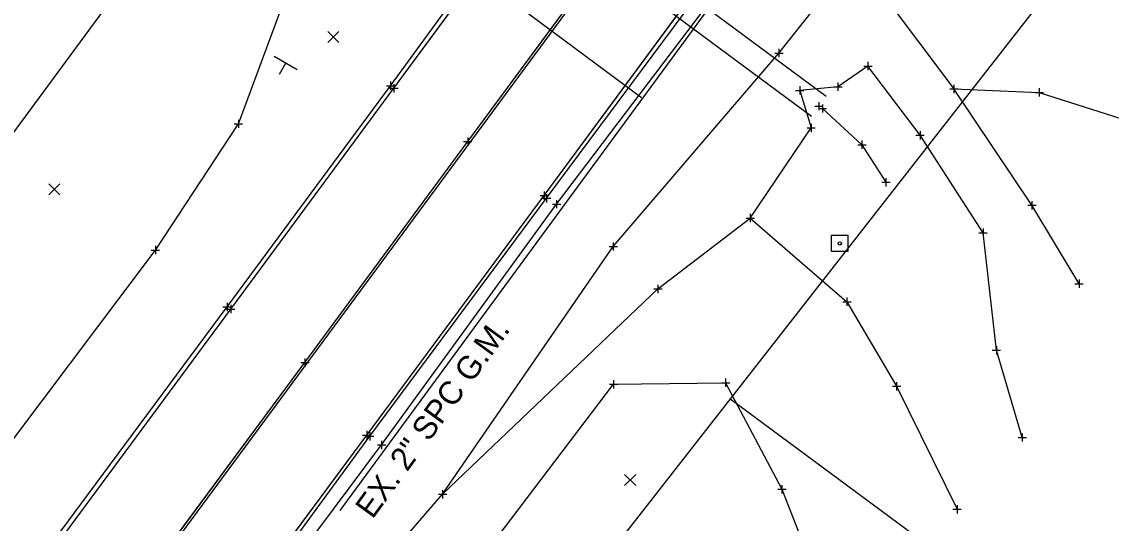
# Model space of a CAD drawing. Extents: x 1324089 to 1329959, y 459099 to 462017.
# Drawn here: x 1325717.7 to 1325849.1, y 460869.9 to 460930.3 of the extents above; entities that cross this region are included whole.
import ezdxf

# ---------------------------------------------------------------- set-up
doc = ezdxf.new("R2010")
doc.units = 0
for name, color, linetype in [('DR_X_Ditch', 7, 'Continuous'), ('DR_X_Storm_Sewer', 7, 'Continuous'), ('DV_X_Property_Line', 7, 'Continuous'), ('PM_X_CL_Double_Solid', 7, 'Continuous'), ('PM_X_Edge_Line', 7, 'Continuous'), ('PM_X_Surveyed_Line', 7, 'Continuous'), ('PV_X_EOP', 7, 'Continuous'), ('RW_X_CL', 7, 'Continuous'), ('RW_X_Fee_RW', 7, 'Continuous'), ('SN_X_Public', 7, 'Continuous'), ('SV_P_Control_Cells_Set', 7, 'Continuous'), ('SV_X_Break_Lines', 7, 'Continuous'), ('SV_X_Random_Point', 7, 'Continuous'), ('SV_X_Shot_Marker', 7, 'Continuous'), ('UT_X_Gas', 7, 'Continuous'), ('UT_X_Gas_Text', 7, 'Continuous'), ('VG_X_Tree_Line_Lt', 7, 'Continuous')]:
    doc.layers.add(name, color=color, linetype=linetype)

msp = doc.modelspace()

# ---------------------------------------------------------------- linework, layer by layer
at = {"layer": 'DR_X_Ditch'}
for points in [[(1325814.27, 460919.9), (1325819.02, 460915.54), (1325821.92, 460911.01)], [(1325618.01, 460663.53), (1325627.67, 460681.57), (1325647.09, 460709.52), (1325667.43, 460737.33), (1325687.6, 460764.77), (1325707.75, 460792.17), (1325728.3, 460821.9), (1325747.65, 460849.3), (1325768.45, 460873.4), (1325794.43, 460898.16), (1325805.56, 460906.69), (1325812.9, 460917.55)]]:
    msp.add_lwpolyline(points, dxfattribs=at)
at = {"layer": 'DR_X_Storm_Sewer'}
for p, q in [((1325764.82, 460958.35), (1325814.73, 460921.37)), ((1325763.03, 460955.94), (1325812.94, 460918.96))]:
    msp.add_line(p, q, dxfattribs=at)
at = {"layer": 'DV_X_Property_Line'}
msp.add_line((1326000.99, 460738.77), (1325803.1, 460884.89), dxfattribs=at)
at = {"layer": 'PM_X_CL_Double_Solid'}
for p, q in [((1325771.48, 460915.92), (1325790.62, 460941.82)), ((1325751.85, 460889.28), (1325771.48, 460915.92)), ((1325731.56, 460861.89), (1325751.85, 460889.28))]:
    msp.add_line(p, q, dxfattribs=at)
at = {"layer": 'PM_X_Edge_Line'}
for p, q in [((1325762.59, 460922.34), (1325781.84, 460948.46)), ((1325780.72, 460909.4), (1325799.76, 460935.26)), ((1325742.91, 460895.72), (1325762.59, 460922.34)), ((1325759.31, 460880.54), (1325780.72, 460909.4)), ((1325722.79, 460868.47), (1325742.91, 460895.72)), ((1325740.27, 460854.83), (1325759.31, 460880.54))]:
    msp.add_line(p, q, dxfattribs=at)
at = {"layer": 'PM_X_Surveyed_Line'}
for points in [[(1325476.47, 460534.64), (1325497.31, 460562.92), (1325518.31, 460591.4), (1325539.27, 460619.83), (1325559.79, 460647.38), (1325579.72, 460674.06), (1325600.34, 460701.82), (1325621.69, 460730.61), (1325640.88, 460756.72), (1325660.89, 460784.38), (1325681.35, 460812.31), (1325701.97, 460840.18), (1325722.79, 460868.47), (1325742.91, 460895.72), (1325762.59, 460922.34), (1325781.84, 460948.46), (1325803.18, 460977.15), (1325823.47, 461004.35), (1325843.8, 461031.8), (1325864.41, 461059.13), (1325882.73, 461083.84)], [(1325487.31, 460531.49), (1325505.56, 460556.21), (1325527.38, 460585.35), (1325547.88, 460612.77), (1325568.5, 460640.75), (1325588.53, 460667.69), (1325609.18, 460695.62), (1325629.78, 460723.42), (1325649.85, 460750.69), (1325670.06, 460778.36), (1325689.99, 460805.97), (1325710.73, 460833.83), (1325731.56, 460861.89), (1325751.85, 460889.28), (1325771.48, 460915.92), (1325790.62, 460941.82), (1325811.71, 460970.27), (1325832.15, 460997.96), (1325852.52, 461025.38), (1325872.84, 461052.92), (1325891.56, 461078.18)], [(1325496.02, 460524.26), (1325516.97, 460552.29), (1325536.74, 460578.69), (1325557.07, 460606.11), (1325577.39, 460633.55), (1325597.52, 460661.26), (1325617.8, 460689.11), (1325638.48, 460716.73), (1325658.71, 460744.05), (1325678.83, 460771.46), (1325699, 460798.96), (1325719.69, 460827.08), (1325740.27, 460854.83), (1325759.31, 460880.54), (1325780.72, 460909.4), (1325799.76, 460935.26), (1325820.52, 460963.73), (1325840.72, 460991.07), (1325861.64, 461019.05), (1325881.76, 461046.3), (1325900.52, 461071.57)]]:
    msp.add_lwpolyline(points, dxfattribs=at)
at = {"layer": 'PV_X_EOP'}
for points in [[(1325599.85, 460702.28), (1325620.93, 460731.2), (1325640.13, 460757.25), (1325660.19, 460784.82), (1325680.81, 460812.72), (1325701.43, 460840.57), (1325722.31, 460868.78), (1325742.47, 460895.99), (1325762.18, 460922.64), (1325781.4, 460948.97), (1325780.32, 460951.92), (1325801.56, 460978.26), (1325816.22, 460999.3), (1325818.01, 460999.23), (1325822.67, 461005.05), (1325842.97, 461032.46), (1325863.41, 461059.87), (1325881.77, 461084.58), (1325817.82, 460998.91)], [(1325599.89, 460659.68), (1325606.14, 460668.13), (1325605.32, 460670.67), (1325618.61, 460688.48), (1325639.21, 460716.24), (1325659.3, 460743.54), (1325679.42, 460770.95), (1325699.67, 460798.43), (1325720.28, 460826.77), (1325740.7, 460854.48), (1325759.66, 460880.4), (1325781, 460909.09), (1325800.15, 460934.9), (1325820.98, 460963.36), (1325841.65, 460990.38), (1325860.1, 461014.66), (1325864.14, 461018.09), (1325883.16, 461043.3), (1325885.35, 461048.43), (1325901.49, 461070.93), (1325836.64, 460984.43)]]:
    msp.add_lwpolyline(points, dxfattribs=at)
at = {"layer": 'RW_X_CL'}
msp.add_line((1325484.96, 460527.54), (1326057.93, 461303.2), dxfattribs=at)
at = {"layer": 'RW_X_Fee_RW'}
for p, q in [((1325448.76, 460554.27), (1326011.05, 461315.47)), ((1325947.56, 461069.64), (1325722.65, 460781.99))]:
    msp.add_line(p, q, dxfattribs=at)
at = {"layer": 'SN_X_Public'}
for p, q in [((1325748.14, 460926.2), (1325750.92, 460924.6)), ((1325749.53, 460925.4), (1325748.73, 460924.01)), ((1325749.53, 460925.4), (1325749.53, 460925.4))]:
    msp.add_line(p, q, dxfattribs=at)
at = {"layer": 'SV_P_Control_Cells_Set'}
msp.add_lwpolyline([(1325815.35, 460904.64), (1325817.33, 460904.64), (1325817.33, 460902.65), (1325815.35, 460902.65), (1325815.35, 460904.64)], dxfattribs=at)
msp.add_circle((1325816.34, 460903.64), 0.2, dxfattribs=at)
at = {"layer": 'SV_X_Break_Lines'}
for points in [[(1325602.57, 460725.5), (1325611.53, 460737.32), (1325631.62, 460762.97), (1325651.12, 460791.06), (1325670.21, 460817.47), (1325692.28, 460846.55), (1325713.18, 460875.42), (1325733.82, 460902.84), (1325743.83, 460918.05), (1325750.81, 460936.82), (1325754.6, 460945.57), (1325761.22, 460957.49), (1325755.79, 460950.52)], [(1325640.49, 460715.25), (1325660.58, 460742.6), (1325680.68, 460770), (1325700.88, 460797.61), (1325721.48, 460825.86), (1325741.85, 460853.59), (1325761.1, 460879.35), (1325782.21, 460908.37), (1325801.61, 460934.01)], [(1325838.36, 460880.25), (1325835.24, 460890.77), (1325833.64, 460904.93), (1325826.04, 460916.67), (1325819.75, 460925.01), (1325816.13, 460922.53), (1325811.52, 460922.08), (1325812.9, 460917.55)], [(1325845.21, 460898.78), (1325839.53, 460908.24), (1325830.12, 460922.26)], [(1325805.56, 460906.69), (1325817.21, 460896.61), (1325823.21, 460886.42), (1325830.5, 460871.6)], [(1325674.96, 460732.24), (1325693.51, 460759.08), (1325711.73, 460788.03), (1325735.94, 460817.21), (1325756.26, 460844.61), (1325775.03, 460868.18), (1325789.08, 460886.67), (1325802.59, 460886.85), (1325809.37, 460874.01), (1325815.93, 460857.25)]]:
    msp.add_lwpolyline(points, dxfattribs=at)
at = {"layer": 'SV_X_Random_Point'}
for p, q in [((1325754.6, 460927.85), (1325755.93, 460929.19)), ((1325754.6, 460929.19), (1325755.93, 460927.85)), ((1325720.96, 460909.49), (1325722.29, 460910.83)), ((1325720.96, 460910.83), (1325722.29, 460909.49)), ((1325790.41, 460874.45), (1325791.74, 460875.78)), ((1325790.41, 460875.78), (1325791.74, 460874.45))]:
    msp.add_line(p, q, dxfattribs=at)
at = {"layer": 'SV_X_Shot_Marker'}
for p, q in [((1325808.51, 460926.58), (1325809.51, 460926.58)), ((1325809.01, 460927.08), (1325809.01, 460926.08)), ((1325809.01, 460926.58), (1325809.01, 460926.58)), ((1325819.25, 460925.01), (1325820.25, 460925.01)), ((1325819.75, 460925.51), (1325819.75, 460924.51)), ((1325819.75, 460925.01), (1325819.75, 460925.01)), ((1325761.68, 460922.64), (1325762.68, 460922.64)), ((1325762.09, 460922.34), (1325763.09, 460922.34)), ((1325762.18, 460923.14), (1325762.18, 460922.14)), ((1325762.18, 460922.64), (1325762.18, 460922.64)), ((1325762.59, 460922.84), (1325762.59, 460921.84)), ((1325762.59, 460922.34), (1325762.59, 460922.34)), ((1325811.02, 460922.08), (1325812.02, 460922.08)), ((1325811.52, 460922.58), (1325811.52, 460921.58)), ((1325811.52, 460922.08), (1325811.52, 460922.08)), ((1325815.63, 460922.53), (1325816.63, 460922.53)), ((1325816.13, 460923.03), (1325816.13, 460922.03)), ((1325816.13, 460922.53), (1325816.13, 460922.53)), ((1325829.62, 460922.26), (1325830.62, 460922.26)), ((1325829.62, 460922.26), (1325830.62, 460922.26)), ((1325830.12, 460922.76), (1325830.12, 460921.76)), ((1325830.12, 460922.76), (1325830.12, 460921.76)), ((1325830.12, 460922.26), (1325830.12, 460922.26)), ((1325830.12, 460922.26), (1325830.12, 460922.26)), ((1325840.4, 460922.34), (1325840.4, 460921.34)), ((1325813.83, 460920.68), (1325813.83, 460919.68)), ((1325839.9, 460921.84), (1325840.9, 460921.84)), ((1325840.4, 460921.84), (1325840.4, 460921.84)), ((1325813.33, 460920.18), (1325814.33, 460920.18)), ((1325813.77, 460919.9), (1325814.77, 460919.9)), ((1325813.83, 460920.18), (1325813.83, 460920.18)), ((1325814.27, 460920.4), (1325814.27, 460919.4)), ((1325814.27, 460919.9), (1325814.27, 460919.9)), ((1325743.33, 460918.05), (1325744.33, 460918.05)), ((1325743.83, 460918.55), (1325743.83, 460917.55)), ((1325743.83, 460918.05), (1325743.83, 460918.05)), ((1325812.9, 460918.05), (1325812.9, 460917.05)), ((1325812.9, 460918.05), (1325812.9, 460917.05)), ((1325812.4, 460917.55), (1325813.4, 460917.55)), ((1325812.4, 460917.55), (1325813.4, 460917.55)), ((1325812.9, 460917.55), (1325812.9, 460917.55)), ((1325812.9, 460917.55), (1325812.9, 460917.55)), ((1325825.54, 460916.67), (1325826.54, 460916.67)), ((1325826.04, 460917.17), (1325826.04, 460916.17)), ((1325826.04, 460916.67), (1325826.04, 460916.67)), ((1325770.98, 460915.92), (1325771.98, 460915.92)), ((1325771.48, 460916.42), (1325771.48, 460915.42)), ((1325771.48, 460915.92), (1325771.48, 460915.92)), ((1325818.52, 460915.54), (1325819.52, 460915.54)), ((1325819.02, 460916.04), (1325819.02, 460915.04)), ((1325819.02, 460915.54), (1325819.02, 460915.54)), ((1325821.92, 460911.51), (1325821.92, 460910.51)), ((1325821.42, 460911.01), (1325822.42, 460911.01)), ((1325821.92, 460911.01), (1325821.92, 460911.01)), ((1325780.22, 460909.4), (1325781.22, 460909.4)), ((1325780.5, 460909.09), (1325781.5, 460909.09)), ((1325780.72, 460909.9), (1325780.72, 460908.9)), ((1325780.72, 460909.4), (1325780.72, 460909.4)), ((1325781, 460909.59), (1325781, 460908.59)), ((1325781, 460909.09), (1325781, 460909.09)), ((1325782.21, 460908.87), (1325782.21, 460907.87)), ((1325781.71, 460908.37), (1325782.71, 460908.37)), ((1325782.21, 460908.37), (1325782.21, 460908.37)), ((1325839.03, 460908.24), (1325840.03, 460908.24)), ((1325839.53, 460908.74), (1325839.53, 460907.74)), ((1325839.53, 460908.24), (1325839.53, 460908.24)), ((1325805.06, 460906.69), (1325806.06, 460906.69)), ((1325805.06, 460906.69), (1325806.06, 460906.69)), ((1325805.56, 460907.19), (1325805.56, 460906.19)), ((1325805.56, 460907.19), (1325805.56, 460906.19)), ((1325805.56, 460906.69), (1325805.56, 460906.69)), ((1325805.56, 460906.69), (1325805.56, 460906.69)), ((1325833.14, 460904.93), (1325834.14, 460904.93)), ((1325833.64, 460905.43), (1325833.64, 460904.43)), ((1325833.64, 460904.93), (1325833.64, 460904.93)), ((1325789.03, 460903.77), (1325789.03, 460902.77)), ((1325733.32, 460902.84), (1325734.32, 460902.84)), ((1325733.82, 460903.34), (1325733.82, 460902.34)), ((1325733.82, 460902.84), (1325733.82, 460902.84)), ((1325788.53, 460903.27), (1325789.53, 460903.27)), ((1325789.03, 460903.27), (1325789.03, 460903.27)), ((1325794.43, 460898.66), (1325794.43, 460897.66)), ((1325844.71, 460898.78), (1325845.71, 460898.78)), ((1325845.21, 460899.28), (1325845.21, 460898.28)), ((1325845.21, 460898.78), (1325845.21, 460898.78)), ((1325793.93, 460898.16), (1325794.93, 460898.16)), ((1325794.43, 460898.16), (1325794.43, 460898.16)), ((1325817.21, 460897.11), (1325817.21, 460896.11)), ((1325741.97, 460895.99), (1325742.97, 460895.99)), ((1325742.41, 460895.72), (1325743.41, 460895.72)), ((1325742.47, 460896.49), (1325742.47, 460895.49)), ((1325742.47, 460895.99), (1325742.47, 460895.99)), ((1325742.91, 460896.22), (1325742.91, 460895.22)), ((1325742.91, 460895.72), (1325742.91, 460895.72)), ((1325816.71, 460896.61), (1325817.71, 460896.61)), ((1325817.21, 460896.61), (1325817.21, 460896.61)), ((1325834.74, 460890.77), (1325835.74, 460890.77)), ((1325835.24, 460891.27), (1325835.24, 460890.27)), ((1325835.24, 460890.77), (1325835.24, 460890.77)), ((1325751.35, 460889.28), (1325752.35, 460889.28)), ((1325751.85, 460889.78), (1325751.85, 460888.78)), ((1325751.85, 460889.28), (1325751.85, 460889.28)), ((1325788.58, 460886.67), (1325789.58, 460886.67)), ((1325789.08, 460887.17), (1325789.08, 460886.17)), ((1325789.08, 460886.67), (1325789.08, 460886.67)), ((1325802.09, 460886.85), (1325803.09, 460886.85)), ((1325802.59, 460887.35), (1325802.59, 460886.35)), ((1325802.59, 460886.85), (1325802.59, 460886.85)), ((1325822.71, 460886.42), (1325823.71, 460886.42)), ((1325823.21, 460886.92), (1325823.21, 460885.92)), ((1325823.21, 460886.42), (1325823.21, 460886.42)), ((1325758.81, 460880.54), (1325759.81, 460880.54)), ((1325759.16, 460880.4), (1325760.16, 460880.4)), ((1325759.31, 460881.04), (1325759.31, 460880.04)), ((1325759.31, 460880.54), (1325759.31, 460880.54)), ((1325759.66, 460880.9), (1325759.66, 460879.9)), ((1325759.66, 460880.4), (1325759.66, 460880.4)), ((1325761.1, 460879.85), (1325761.1, 460878.85)), ((1325837.86, 460880.25), (1325838.86, 460880.25)), ((1325838.36, 460880.75), (1325838.36, 460879.75)), ((1325838.36, 460880.25), (1325838.36, 460880.25)), ((1325760.6, 460879.35), (1325761.6, 460879.35)), ((1325761.1, 460879.35), (1325761.1, 460879.35)), ((1325767.95, 460873.4), (1325768.95, 460873.4)), ((1325767.95, 460873.4), (1325768.95, 460873.4)), ((1325768.45, 460873.9), (1325768.45, 460872.9)), ((1325768.45, 460873.9), (1325768.45, 460872.9)), ((1325768.45, 460873.4), (1325768.45, 460873.4)), ((1325768.45, 460873.4), (1325768.45, 460873.4)), ((1325808.87, 460874.01), (1325809.87, 460874.01)), ((1325809.37, 460874.51), (1325809.37, 460873.51)), ((1325809.37, 460874.01), (1325809.37, 460874.01)), ((1325830.5, 460872.1), (1325830.5, 460871.1)), ((1325830, 460871.6), (1325831, 460871.6)), ((1325830.5, 460871.6), (1325830.5, 460871.6))]:
    msp.add_line(p, q, dxfattribs=at)
at = {"layer": 'UT_X_Gas'}
for p, q in [((1325756.11, 460871.47), (1326071.48, 461301.36)), ((1325761.23, 460944.39), (1325792.46, 460921.24))]:
    msp.add_line(p, q, dxfattribs=at)
at = {"layer": 'VG_X_Tree_Line_Lt'}
msp.add_lwpolyline([(1325561.25, 460522.54), (1325554.26, 460534.28), (1325569.47, 460555.09), (1325586.69, 460584.7), (1325603.84, 460612.45), (1325615.02, 460649.1), (1325618.01, 460663.53), (1325627.67, 460681.57), (1325647.09, 460709.52), (1325667.43, 460737.33), (1325687.6, 460764.77), (1325707.75, 460792.17), (1325728.3, 460821.9), (1325747.65, 460849.3), (1325768.45, 460873.4), (1325789.03, 460903.27), (1325809.01, 460926.58), (1325817.6, 460937.41), (1325821.57, 460933.63), (1325830.12, 460922.26), (1325840.4, 460921.84), (1325857.57, 460916.36)], dxfattribs=at)

# ---------------------------------------------------------------- texts
at = {"layer": 'UT_X_Gas_Text'}
msp.add_text('EX. 2" SPC G.M.', height=2.8, rotation=53.9419, dxfattribs=at).set_placement((1325760, 460870.32))

doc.saveas('drawing.dxf')
